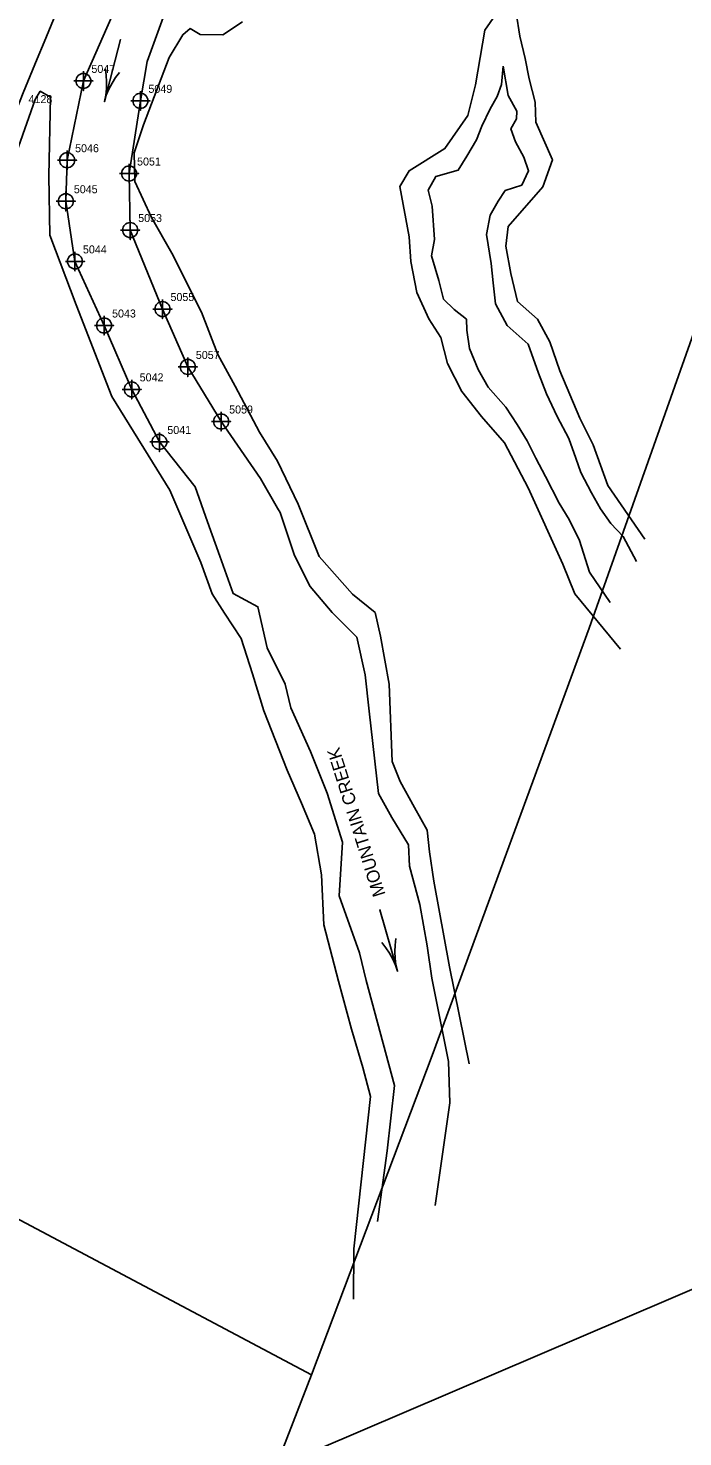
# Model space of a CAD drawing. Extents: x 1653123 to 1656194, y 596584 to 600233.
# Drawn here: x 1653621.2 to 1653825.7, y 597270.9 to 597710.9 of the extents above; entities that cross this region are included whole.
import ezdxf

# ---------------------------------------------------------------- set-up
doc = ezdxf.new("R2010")
doc.units = 0
for name, color, linetype in [('Exist Horizontal Alignment', 7, 'Continuous'), ('Exist Hydro Jurisdictional Stream or Body of Water', 7, 'Continuous'), ('Exist Hydro River Flow Arrow CELL', 7, 'Continuous'), ('Exist Hydro Stream or Body of Water Cogo Number', 7, 'Continuous'), ('Exist Hydro Stream or Body of Water Text', 7, 'Continuous'), ('Exist Other Culture Anchor (Guy Wire) Cogo Number', 7, 'Continuous'), ('Exist Property Line', 7, 'Continuous'), ('Exist Right of Way Line', 7, 'Continuous'), ('Exist Vegetation Woods Line', 7, 'Continuous'), ('Prop Easement Construction Station Offsets', 7, 'Continuous'), ('Prop Guardrail', 7, 'Continuous'), ('Prop Guardrail Anchor Unit CELL', 7, 'Continuous')]:
    doc.layers.add(name, color=color, linetype=linetype)

msp = doc.modelspace()

# ---------------------------------------------------------------- linework, layer by layer
at = {"layer": 'Exist Horizontal Alignment'}
msp.add_arc((1655696.35, 596851.16), 2270, 149.9451, 159.30371, dxfattribs=at)
at = {"layer": 'Exist Hydro Jurisdictional Stream or Body of Water'}
for points in [[(1653638.42, 597694.46), (1653659.64, 597742.65), (1653662.65, 597748.06), (1653666.74, 597759.91), (1653664.11, 597772.59), (1653666.67, 597779.65)], [(1653693.8, 597570.3), (1653681.46, 597588.06), (1653671.05, 597605.1), (1653663.13, 597623.2), (1653653.04, 597647.87), (1653652.69, 597665.53), (1653656.24, 597688.24), (1653658.32, 597700.51), (1653666.26, 597722.43)], [(1653673.36, 597567.62), (1653662.15, 597581.66), (1653653.51, 597598.1), (1653644.88, 597618.05), (1653635.78, 597638.08), (1653632.93, 597656.87), (1653633.33, 597669.69), (1653638.42, 597694.46)], [(1653730.31, 597338.15), (1653733.3, 597360.25), (1653735.59, 597380.58), (1653726.77, 597413.37), (1653724.68, 597422.09), (1653718.33, 597439.83), (1653719.39, 597456.62), (1653714.63, 597471.94), (1653709.35, 597484.96), (1653703.23, 597498.64), (1653701.49, 597505.96), (1653695.84, 597517.3), (1653692.94, 597530.19), (1653685.26, 597534.29), (1653681.04, 597545.95), (1653677.22, 597556.74), (1653673.36, 597567.62)], [(1653748.38, 597343.13), (1653752.92, 597375.18), (1653752.53, 597388.08), (1653747.32, 597414.13), (1653745.83, 597424.27), (1653743.51, 597437.16), (1653740.34, 597449.18), (1653739.97, 597455.84), (1653734.8, 597464.37), (1653730.63, 597471.84), (1653727.72, 597497.54), (1653726.43, 597508.93), (1653723.85, 597520.64), (1653716.2, 597528.43), (1653709.28, 597536.53), (1653704.34, 597546.18), (1653699.9, 597559.63), (1653699.11, 597560.99), (1653693.8, 597570.3)]]:
    msp.add_lwpolyline(points, dxfattribs=at)
at = {"layer": 'Exist Hydro River Flow Arrow CELL'}
for p, q in [((1653647.49, 597697.71), (1653647.49, 597697.71)), ((1653733.83, 597425.9), (1653733.83, 597425.9))]:
    msp.add_line(p, q, dxfattribs=at)
for points in [[(1653649.7, 597697.14), (1653648.47, 597695.51), (1653647.36, 597693.76), (1653646.39, 597691.9), (1653645.57, 597690), (1653644.98, 597688.03), (1653650, 597707.39), (1653644.98, 597688.03), (1653645.42, 597690.04), (1653645.63, 597692.1), (1653645.69, 597694.19), (1653645.56, 597696.26), (1653645.28, 597698.29)], [(1653736.03, 597426.53), (1653735.79, 597424.5), (1653735.72, 597422.43), (1653735.83, 597420.34), (1653736.09, 597418.28), (1653736.59, 597416.29), (1653731.07, 597435.51), (1653736.59, 597416.29), (1653735.95, 597418.24), (1653735.08, 597420.12), (1653734.06, 597421.95), (1653732.91, 597423.67), (1653731.63, 597425.27)]]:
    msp.add_lwpolyline(points, dxfattribs=at)
at = {"layer": 'Exist Property Line'}
msp.add_line((1653533.72, 597190.94), (1653865.73, 597332.78), dxfattribs=at)
at = {"layer": 'Exist Right of Way Line'}
for radius in [2300, 2240]:
    msp.add_arc((1655696.35, 596851.16), radius, 149.9451, 159.30371, dxfattribs=at)
at = {"layer": 'Exist Vegetation Woods Line'}
for points in [[(1653768.88, 597717.51), (1653763.81, 597710.37), (1653760.97, 597693.22), (1653758.51, 597683.64), (1653751.38, 597673.31), (1653740.26, 597666.4), (1653737.28, 597661.43), (1653740.21, 597645.72), (1653740.69, 597638.01), (1653742.61, 597628.38), (1653746.38, 597620.11), (1653750.12, 597614.32), (1653752.19, 597606.14), (1653756.72, 597597.43), (1653762.85, 597589.66), (1653769.96, 597581.4), (1653777.42, 597567.37), (1653788.21, 597543.5), (1653791.95, 597534.27), (1653806.27, 597516.98)], [(1653758.94, 597387.34), (1653752.84, 597417.68), (1653747.94, 597444.5), (1653746.58, 597453.61), (1653745.87, 597460.43), (1653741.9, 597467.43), (1653737.39, 597475.64), (1653734.94, 597481.8), (1653733.99, 597506.05), (1653731.26, 597520.99), (1653729.57, 597528.37), (1653722.52, 597534.1), (1653712.12, 597545.89), (1653705.52, 597562.26), (1653699.12, 597575.65), (1653693.4, 597584.76), (1653685.83, 597599.08), (1653680.41, 597608.95), (1653675.37, 597622.25), (1653666.05, 597640.66), (1653659.66, 597651.8), (1653654.45, 597663.08), (1653654.28, 597671.95), (1653657.21, 597680.71), (1653665.26, 597701.78), (1653669.44, 597708.89), (1653671.73, 597710.8), (1653674.94, 597708.92), (1653682.04, 597708.83), (1653688.1, 597712.91)], [(1653813.87, 597551.28), (1653802.29, 597568.06), (1653797.68, 597580.76), (1653793.57, 597589.14), (1653787.28, 597603.89), (1653784.16, 597612.96), (1653780.32, 597620.01), (1653774.02, 597625.57), (1653772.03, 597634.33), (1653770.42, 597642.8), (1653771.17, 597648.94), (1653782.01, 597661.35), (1653784.97, 597669.8), (1653779.81, 597681.61), (1653779.54, 597687.79), (1653777.69, 597695.09), (1653776.41, 597701.44), (1653774.75, 597708.46), (1653773.66, 597715.73)], [(1653612.18, 597657.29), (1653623.35, 597688.62), (1653624.93, 597691.25), (1653628.15, 597689.36), (1653627.57, 597664.77), (1653627.96, 597646.24), (1653636.18, 597624.54), (1653647.33, 597595.92), (1653665.39, 597566.66), (1653675.16, 597543.97), (1653678.64, 597534.18), (1653682.54, 597528.21), (1653687.76, 597520.22), (1653691.29, 597509.27), (1653694.78, 597497.66), (1653702.05, 597479.14), (1653706.56, 597468.83), (1653710.61, 597459.17), (1653712.87, 597446.45), (1653713.53, 597430.78), (1653718.12, 597413.26), (1653722.23, 597398.17), (1653725.77, 597386.27), (1653728.08, 597377.22), (1653722.96, 597329.62), (1653722.78, 597313.9)]]:
    msp.add_lwpolyline(points, dxfattribs=at)
at = {"layer": 'Prop Easement Construction Station Offsets'}
for points in [[(1653802.99, 597531.53), (1653796.52, 597540.96), (1653793.43, 597550.84), (1653790.23, 597557.42), (1653787.1, 597562.59), (1653782.77, 597570.9), (1653779.81, 597576.56), (1653777.06, 597582.06), (1653773.92, 597587.09), (1653770.39, 597592.51), (1653764.91, 597598.77), (1653761.75, 597604.27), (1653759.08, 597610.83), (1653758.2, 597616.64), (1653758.13, 597620), (1653754.24, 597623.03), (1653750.92, 597626.28), (1653749.52, 597632.15), (1653747.21, 597639.85), (1653748.08, 597644.91), (1653747.39, 597655.3), (1653746.19, 597660.34), (1653748.54, 597664.6), (1653755.57, 597666.54), (1653758.22, 597670.96), (1653761.27, 597676.1), (1653762.9, 597680.37), (1653765.51, 597685.79), (1653767.74, 597689.59), (1653769.04, 597693.3), (1653769.63, 597699.07)], [(1653769.63, 597699.07), (1653771.17, 597689.87), (1653773.89, 597685.02), (1653773.73, 597682.59), (1653771.93, 597679.53), (1653773.4, 597675.4), (1653776.07, 597670.61), (1653777.54, 597666.42), (1653775.37, 597661.91), (1653770.23, 597660.22), (1653768.07, 597656.89), (1653765.49, 597652.5), (1653764.39, 597646.5), (1653765.8, 597637.42), (1653766.49, 597631.38), (1653767.24, 597624.81), (1653770.81, 597618.01), (1653777.37, 597612.25), (1653780.66, 597603.11), (1653783.12, 597596.68), (1653786.41, 597589.62), (1653790.12, 597582.74), (1653792.33, 597576.6), (1653793.88, 597572.12), (1653797.18, 597565.78), (1653799.99, 597560.74), (1653803.27, 597556.19), (1653807.06, 597552.16), (1653811.25, 597544.32)]]:
    msp.add_lwpolyline(points, dxfattribs=at)
at = {"layer": 'Prop Guardrail'}
for points in [[(1653467.13, 598020.82), (1653523.07, 597987.98), (1653581.92, 597953.42), (1653657.82, 597908.84), (1653672.02, 597900.5), (1653696.02, 597886.41), (1653711.71, 597877.2), (1653903.59, 597776.41), (1653848.79, 597671.21), (1653796.49, 597523.51), (1653747.41, 597390), (1653709.73, 597290.27), (1653571.5, 597363.59), (1653527.51, 597387.98), (1653462.99, 597422.58), (1653451.94, 597428.93), (1653267.19, 597532.81), (1653332.24, 597710), (1653352.48, 597767.52), (1653388.58, 597870)], [(1653709.73, 597290.27), (1653571.5, 597363.59), (1653527.51, 597387.98), (1653462.99, 597422.58), (1653451.94, 597428.93), (1653370.95, 597472.92), (1653325.16, 597498.99), (1653267.19, 597532.81), (1653227.64, 597430), (1653210, 597385.17), (1653175.68, 597310), (1653122.76, 597255.96), (1653228.72, 597150), (1653290, 597088.72), (1653308.72, 597070), (1653330, 597048.72), (1653379.36, 596999.36), (1653428.72, 596950), (1653476.31, 596902.41), (1653526.95, 596953.05), (1653570, 596996.1), (1653592.12, 597018.22), (1653654.2, 597154.2), (1653672.62, 597194.56)]]:
    msp.add_lwpolyline(points, close=True, dxfattribs=at)
at = {"layer": 'Prop Guardrail Anchor Unit CELL'}
for points in [[(1653635.42, 597694.46), (1653641.42, 597694.46), (1653638.42, 597694.46), (1653638.42, 597691.46), (1653638.42, 597697.46)], [(1653653.24, 597688.24), (1653659.24, 597688.24), (1653656.24, 597688.24), (1653656.24, 597685.24), (1653656.24, 597691.24)], [(1653630.33, 597669.69), (1653636.33, 597669.69), (1653633.33, 597669.69), (1653633.33, 597666.69), (1653633.33, 597672.69)], [(1653649.69, 597665.53), (1653655.69, 597665.53), (1653652.69, 597665.53), (1653652.69, 597662.53), (1653652.69, 597668.53)], [(1653629.93, 597656.87), (1653635.93, 597656.87), (1653632.93, 597656.87), (1653632.93, 597653.87), (1653632.93, 597659.87)], [(1653650.04, 597647.87), (1653656.04, 597647.87), (1653653.04, 597647.87), (1653653.04, 597644.87), (1653653.04, 597650.87)], [(1653632.78, 597638.08), (1653638.78, 597638.08), (1653635.78, 597638.08), (1653635.78, 597635.08), (1653635.78, 597641.08)], [(1653660.13, 597623.2), (1653666.13, 597623.2), (1653663.13, 597623.2), (1653663.13, 597620.2), (1653663.13, 597626.2)], [(1653641.88, 597618.05), (1653647.88, 597618.05), (1653644.88, 597618.05), (1653644.88, 597615.05), (1653644.88, 597621.05)], [(1653668.05, 597605.1), (1653674.05, 597605.1), (1653671.05, 597605.1), (1653671.05, 597602.1), (1653671.05, 597608.1)], [(1653650.51, 597598.1), (1653656.51, 597598.1), (1653653.51, 597598.1), (1653653.51, 597595.1), (1653653.51, 597601.1)], [(1653678.46, 597588.06), (1653684.46, 597588.06), (1653681.46, 597588.06), (1653681.46, 597585.06), (1653681.46, 597591.06)], [(1653659.15, 597581.66), (1653665.15, 597581.66), (1653662.15, 597581.66), (1653662.15, 597578.66), (1653662.15, 597584.66)]]:
    msp.add_lwpolyline(points, dxfattribs=at)
for centre in [(1653638.42, 597694.46), (1653656.24, 597688.24), (1653633.33, 597669.69), (1653652.69, 597665.53), (1653632.93, 597656.87), (1653653.04, 597647.87), (1653635.78, 597638.08), (1653663.13, 597623.2), (1653644.88, 597618.05), (1653671.05, 597605.1), (1653653.51, 597598.1), (1653681.46, 597588.06), (1653662.15, 597581.66)]:
    msp.add_circle(centre, 2.34, dxfattribs=at)

# ---------------------------------------------------------------- texts
at = {"layer": 'Exist Hydro Stream or Body of Water Cogo Number'}
for s, p in [('5047', (1653640.92, 597696.96)), ('5049', (1653658.74, 597690.74)), ('5046', (1653635.83, 597672.19)), ('5051', (1653655.19, 597668.03)), ('5045', (1653635.43, 597659.37)), ('5053', (1653655.54, 597650.37)), ('5044', (1653638.28, 597640.58)), ('5055', (1653665.63, 597625.7)), ('5043', (1653647.38, 597620.55)), ('5057', (1653673.55, 597607.6)), ('5042', (1653656.01, 597600.6)), ('5059', (1653683.96, 597590.56)), ('5041', (1653664.65, 597584.16))]:
    msp.add_text(s, height=2.5, dxfattribs=at).set_placement(p)
at = {"layer": 'Exist Hydro Stream or Body of Water Text'}
msp.add_text(' MOUNTAIN CREEK', height=4, rotation=107.4828, dxfattribs=at).set_placement((1653733.31, 597438.92))
at = {"layer": 'Exist Other Culture Anchor (Guy Wire) Cogo Number'}
msp.add_text('4128', height=2.5, dxfattribs=at).set_placement((1653621.28, 597687.52))

doc.saveas('drawing.dxf')
